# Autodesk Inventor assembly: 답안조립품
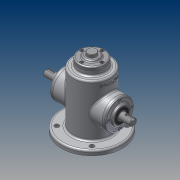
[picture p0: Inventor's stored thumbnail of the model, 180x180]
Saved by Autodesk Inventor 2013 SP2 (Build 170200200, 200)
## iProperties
Created: 2014-12
Part Number: 답안조립품
Document SubType Name: Assembly
Designer: CADB301
Author: CADB301
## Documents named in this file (12)
- C:\Users\CADB301\Desktop\441228V1020\답안조립품.iam
- C:\Users\CADB301\Desktop\441228V1020\본체.ipt
- C:\Users\CADB301\Desktop\441228V1020\M3x0.5x8.ipt
- M3x0.5.ipt
- C:\Users\CADB301\Desktop\441228V1020\베어링 6002.ipt
- 베어링 6002.ipt
- C:\Users\CADB301\Desktop\441228V1020\상단커버.ipt
- C:\Users\CADB301\Desktop\441228V1020\슬라이드.ipt
- C:\Users\CADB301\Desktop\441228V1020\오일실.ipt
- 오일실.ipt
- C:\Users\CADB301\Desktop\441228V1020\커버.ipt
- C:\Users\CADB301\Desktop\441228V1020\편심축.ipt
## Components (8 placed, 1 different names)
1. M3x0.5:1
2. M3x0.5:3
3. M3x0.5:4
4. M3x0.5:5
5. M3x0.5:2
6. M3x0.5:6
7. M3x0.5:7
8. M3x0.5:8
